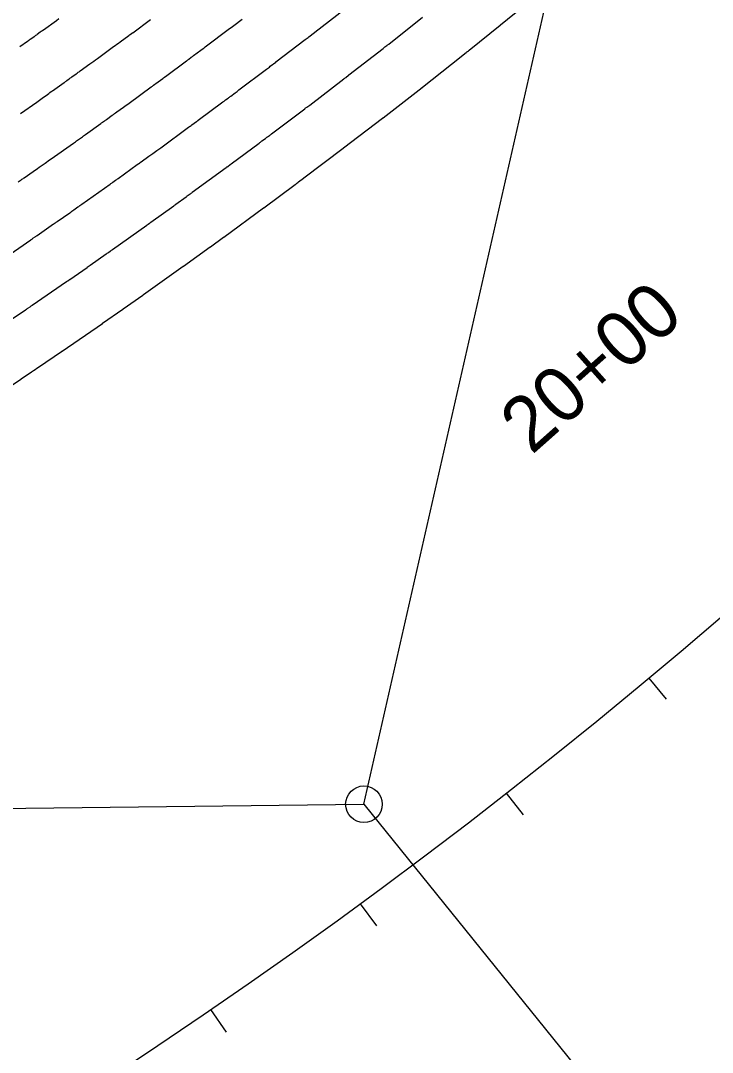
# Model space of a CAD drawing. Extents: x 1710723 to 1713003, y 548603 to 551142.
# Drawn here: x 1712116.1 to 1712191.7, y 549190 to 549302.6 of the extents above; entities that cross this region are included whole.
import ezdxf

# ---------------------------------------------------------------- set-up
doc = ezdxf.new("R2010")
doc.units = 0
for name, color, linetype in [('R_Contours', 7, 'Continuous'), ('R_Horz Alg', 7, 'Continuous'), ('R_Horz Alg Annot', 7, 'Continuous')]:
    doc.layers.add(name, color=color, linetype=linetype)

msp = doc.modelspace()

# ---------------------------------------------------------------- linework, layer by layer
at = {"layer": 'R_Contours'}
for points in [[(1712111.69, 549260.5), (1712116.15, 549263.48), (1712116.18, 549263.5), (1712117.33, 549264.28), (1712117.53, 549264.41), (1712117.72, 549264.54), (1712117.91, 549264.67), (1712118.1, 549264.8), (1712120.6, 549266.5), (1712120.65, 549266.54), (1712120.66, 549266.54), (1712125.06, 549269.57), (1712125.09, 549269.59), (1712127.31, 549271.14), (1712127.34, 549271.16), (1712129.48, 549272.67), (1712129.5, 549272.68), (1712129.53, 549272.7), (1712129.54, 549272.71), (1712133.9, 549275.8), (1712133.93, 549275.83), (1712136.85, 549277.93), (1712136.86, 549277.94), (1712138.29, 549278.97), (1712138.33, 549279), (1712138.33, 549279), (1712142.66, 549282.18), (1712142.7, 549282.2), (1712146.12, 549284.74), (1712146.21, 549284.81), (1712146.3, 549284.88), (1712146.39, 549284.95), (1712146.48, 549285.01), (1712147.02, 549285.41), (1712147.03, 549285.43), (1712147.06, 549285.45), (1712147.07, 549285.45), (1712151.35, 549288.69), (1712151.39, 549288.72), (1712155.65, 549291.98), (1712155.69, 549292.01), (1712155.72, 549292.03), (1712159.97, 549295.34), (1712160, 549295.37), (1712160.01, 549295.37), (1712164.25, 549298.72), (1712164.28, 549298.74), (1712164.78, 549299.14), (1712164.86, 549299.2), (1712164.94, 549299.27), (1712165.03, 549299.34), (1712165.11, 549299.4), (1712168.5, 549302.13), (1712168.53, 549302.15), (1712172.74, 549305.58)], [(1712114.14, 549276.56), (1712117.25, 549278.7), (1712117.3, 549278.74), (1712117.36, 549278.78), (1712117.42, 549278.82), (1712117.48, 549278.86), (1712117.71, 549279.02), (1712117.77, 549279.06), (1712117.82, 549279.1), (1712117.88, 549279.14), (1712117.94, 549279.18), (1712119.46, 549280.24), (1712119.52, 549280.28), (1712119.57, 549280.31), (1712119.63, 549280.35), (1712119.69, 549280.39), (1712119.91, 549280.55), (1712119.96, 549280.58), (1712120.02, 549280.62), (1712120.07, 549280.66), (1712120.13, 549280.7), (1712121.49, 549281.65), (1712121.6, 549281.73), (1712121.71, 549281.81), (1712121.82, 549281.89), (1712121.93, 549281.97), (1712122.38, 549282.28), (1712122.49, 549282.35), (1712122.6, 549282.43), (1712122.71, 549282.51), (1712122.82, 549282.59), (1712125.9, 549284.77), (1712125.97, 549284.83), (1712126.04, 549284.88), (1712126.12, 549284.93), (1712126.19, 549284.98), (1712126.49, 549285.19), (1712126.56, 549285.24), (1712126.63, 549285.29), (1712126.71, 549285.35), (1712126.78, 549285.4), (1712128.87, 549286.9), (1712128.9, 549286.93), (1712128.94, 549286.95), (1712128.97, 549286.98), (1712129.01, 549287), (1712129.15, 549287.11), (1712129.19, 549287.13), (1712129.23, 549287.16), (1712129.26, 549287.18), (1712129.3, 549287.21), (1712130.14, 549287.82), (1712130.25, 549287.9), (1712130.36, 549287.98), (1712130.47, 549288.06), (1712130.57, 549288.13), (1712131.01, 549288.44), (1712131.11, 549288.52), (1712131.22, 549288.6), (1712131.33, 549288.68), (1712131.44, 549288.75), (1712134.48, 549290.98), (1712134.57, 549291.05), (1712134.66, 549291.11), (1712134.74, 549291.18), (1712134.83, 549291.24), (1712135.33, 549291.6), (1712135.37, 549291.63), (1712135.4, 549291.66), (1712135.47, 549291.71), (1712135.51, 549291.73), (1712135.54, 549291.76), (1712138.22, 549293.75), (1712138.29, 549293.8), (1712138.36, 549293.85), (1712138.43, 549293.91), (1712138.5, 549293.96), (1712138.79, 549294.17), (1712138.86, 549294.23), (1712138.93, 549294.28), (1712139, 549294.33), (1712139.08, 549294.39), (1712139.56, 549294.75), (1712139.67, 549294.82), (1712139.77, 549294.9), (1712139.88, 549294.98), (1712139.98, 549295.06), (1712142.99, 549297.33), (1712143.09, 549297.41), (1712143.19, 549297.48), (1712143.3, 549297.56), (1712143.4, 549297.64), (1712144.02, 549298.1), (1712144.02, 549298.11), (1712147.21, 549300.55), (1712147.31, 549300.63), (1712147.42, 549300.71), (1712147.52, 549300.78), (1712147.62, 549300.86), (1712148.23, 549301.33), (1712148.25, 549301.35), (1712151.45, 549303.83)], [(1712114.57, 549269.62), (1712116.68, 549271.06), (1712116.74, 549271.1), (1712116.8, 549271.14), (1712116.86, 549271.19), (1712116.92, 549271.23), (1712117.16, 549271.39), (1712117.22, 549271.43), (1712117.28, 549271.47), (1712117.34, 549271.51), (1712117.4, 549271.55), (1712121.15, 549274.13), (1712121.18, 549274.16), (1712121.21, 549274.18), (1712121.24, 549274.2), (1712121.27, 549274.22), (1712121.39, 549274.3), (1712121.42, 549274.32), (1712121.45, 549274.34), (1712121.48, 549274.36), (1712121.51, 549274.38), (1712123.39, 549275.69), (1712123.42, 549275.71), (1712123.44, 549275.73), (1712123.47, 549275.75), (1712123.5, 549275.77), (1712123.62, 549275.85), (1712123.65, 549275.87), (1712123.68, 549275.89), (1712123.71, 549275.91), (1712123.73, 549275.93), (1712125.49, 549277.16), (1712125.54, 549277.2), (1712125.6, 549277.24), (1712125.66, 549277.28), (1712125.72, 549277.32), (1712125.95, 549277.49), (1712126.01, 549277.53), (1712126.07, 549277.57), (1712126.12, 549277.61), (1712126.18, 549277.65), (1712129.9, 549280.29), (1712129.94, 549280.32), (1712129.97, 549280.34), (1712130.01, 549280.37), (1712130.05, 549280.4), (1712130.2, 549280.51), (1712130.24, 549280.53), (1712130.28, 549280.56), (1712130.32, 549280.59), (1712130.36, 549280.61), (1712132.86, 549282.41), (1712132.89, 549282.44), (1712132.93, 549282.47), (1712133.01, 549282.52), (1712133.03, 549282.53), (1712133.04, 549282.55), (1712133.06, 549282.56), (1712133.08, 549282.57), (1712134.22, 549283.4), (1712134.27, 549283.44), (1712134.33, 549283.48), (1712134.38, 549283.52), (1712134.44, 549283.56), (1712134.66, 549283.72), (1712134.72, 549283.76), (1712134.77, 549283.8), (1712134.83, 549283.84), (1712134.88, 549283.88), (1712138.57, 549286.58), (1712138.62, 549286.61), (1712138.66, 549286.65), (1712138.71, 549286.68), (1712138.75, 549286.71), (1712139.01, 549286.9), (1712139.05, 549286.93), (1712139.09, 549286.96), (1712139.12, 549286.98), (1712142.17, 549289.25), (1712142.25, 549289.31), (1712142.33, 549289.37), (1712142.41, 549289.43), (1712142.49, 549289.49), (1712142.87, 549289.77), (1712142.93, 549289.81), (1712142.98, 549289.85), (1712143.03, 549289.89), (1712143.09, 549289.93), (1712143.31, 549290.09), (1712143.36, 549290.13), (1712143.41, 549290.17), (1712143.47, 549290.21), (1712143.52, 549290.25), (1712147.17, 549293.01), (1712147.22, 549293.05), (1712147.28, 549293.09), (1712147.33, 549293.13), (1712147.38, 549293.17), (1712147.71, 549293.41), (1712147.71, 549293.41), (1712151.43, 549296.26), (1712151.48, 549296.3), (1712151.54, 549296.34), (1712151.59, 549296.39), (1712151.64, 549296.43), (1712151.95, 549296.66), (1712151.98, 549296.69), (1712155.71, 549299.59), (1712155.76, 549299.63), (1712155.81, 549299.67), (1712155.87, 549299.71), (1712155.92, 549299.75), (1712156.13, 549299.91), (1712156.18, 549299.95), (1712156.23, 549299.99), (1712156.28, 549300.03), (1712156.33, 549300.07), (1712160.04, 549302.99)], [(1712115.87, 549285.01), (1712116.2, 549285.24), (1712116.28, 549285.3), (1712116.36, 549285.35), (1712116.44, 549285.41), (1712116.52, 549285.47), (1712117.49, 549286.15), (1712117.66, 549286.26), (1712117.82, 549286.38), (1712117.99, 549286.49), (1712118.15, 549286.61), (1712118.81, 549287.07), (1712118.97, 549287.18), (1712119.14, 549287.3), (1712119.3, 549287.41), (1712119.47, 549287.53), (1712121.9, 549289.26), (1712122.01, 549289.33), (1712122.11, 549289.41), (1712122.22, 549289.49), (1712122.33, 549289.57), (1712122.77, 549289.87), (1712122.88, 549289.95), (1712122.99, 549290.03), (1712123.1, 549290.11), (1712123.2, 549290.18), (1712124.88, 549291.39), (1712124.93, 549291.43), (1712124.98, 549291.46), (1712125.04, 549291.5), (1712125.09, 549291.54), (1712125.3, 549291.69), (1712125.36, 549291.73), (1712125.41, 549291.77), (1712125.46, 549291.81), (1712125.51, 549291.84), (1712126.14, 549292.3), (1712126.27, 549292.39), (1712126.39, 549292.48), (1712126.51, 549292.57), (1712126.64, 549292.65), (1712127.35, 549293.17), (1712127.51, 549293.28), (1712127.67, 549293.4), (1712127.83, 549293.51), (1712127.99, 549293.63), (1712130.38, 549295.39), (1712130.52, 549295.48), (1712130.65, 549295.58), (1712130.78, 549295.67), (1712130.91, 549295.77), (1712131.65, 549296.31), (1712131.7, 549296.34), (1712131.75, 549296.38), (1712131.86, 549296.46), (1712131.88, 549296.48), (1712131.91, 549296.5), (1712131.93, 549296.52), (1712131.96, 549296.54), (1712134.26, 549298.25), (1712134.33, 549298.29), (1712134.39, 549298.34), (1712134.45, 549298.39), (1712134.51, 549298.43), (1712134.76, 549298.62), (1712134.82, 549298.67), (1712134.89, 549298.71), (1712134.95, 549298.76), (1712135.01, 549298.8), (1712135.82, 549299.4), (1712135.97, 549299.52), (1712136.13, 549299.63), (1712136.28, 549299.75), (1712136.44, 549299.86), (1712138.8, 549301.65), (1712138.95, 549301.76), (1712139.11, 549301.88), (1712139.26, 549301.99), (1712139.41, 549302.11), (1712140.33, 549302.79)], [(1712120.3, 549302.81), (1712120.04, 549302.62), (1712118.62, 549301.6), (1712118.54, 549301.54), (1712118.45, 549301.48), (1712118.37, 549301.42), (1712118.28, 549301.36), (1712117.94, 549301.11), (1712117.86, 549301.05), (1712117.77, 549300.99), (1712117.69, 549300.93), (1712117.6, 549300.87), (1712117.25, 549300.61), (1712117.16, 549300.55), (1712117.07, 549300.49), (1712116.98, 549300.42), (1712116.89, 549300.36), (1712116.04, 549299.75)], [(1712116.11, 549292.47), (1712117.9, 549293.74), (1712118.04, 549293.84), (1712118.18, 549293.95), (1712118.33, 549294.05), (1712118.47, 549294.15), (1712119.05, 549294.56), (1712119.2, 549294.66), (1712119.34, 549294.76), (1712119.48, 549294.87), (1712119.63, 549294.97), (1712120.89, 549295.87), (1712120.96, 549295.92), (1712121.03, 549295.98), (1712121.1, 549296.03), (1712121.17, 549296.08), (1712121.45, 549296.28), (1712121.52, 549296.33), (1712121.59, 549296.38), (1712121.66, 549296.43), (1712121.73, 549296.48), (1712122.21, 549296.83), (1712122.32, 549296.9), (1712122.42, 549296.98), (1712122.52, 549297.05), (1712122.63, 549297.13), (1712123.69, 549297.89), (1712123.9, 549298.04), (1712124.11, 549298.2), (1712124.32, 549298.35), (1712124.54, 549298.5), (1712126.29, 549299.79), (1712126.47, 549299.92), (1712126.64, 549300.04), (1712126.81, 549300.17), (1712126.99, 549300.3), (1712127.96, 549301.01), (1712128, 549301.03), (1712128.03, 549301.06), (1712128.07, 549301.08), (1712128.1, 549301.11), (1712128.24, 549301.21), (1712128.28, 549301.24), (1712128.31, 549301.26), (1712128.34, 549301.29), (1712128.38, 549301.31), (1712130.31, 549302.75)]]:
    msp.add_lwpolyline(points, dxfattribs=at)
at = {"layer": 'R_Horz Alg'}
for centre, radius, start, end in [((1711727.02, 549745.3), 532.98, 270.6428, 347.2066), ((1711777.17, 549719.88), 636.62, 271.07865, 340.7734)]:
    msp.add_arc(centre, radius, start, end, dxfattribs=at)
at = {"layer": 'R_Horz Alg Annot'}
for p, q in [((1712153.63, 549217.07), (1712246.77, 549627.28)), ((1711733, 549212.35), (1712153.63, 549217.07))]:
    msp.add_line(p, q, dxfattribs=at)
for points in [[(1712186.68, 549228.53), (1712184.76, 549230.84)], [(1712171.04, 549215.91), (1712169.19, 549218.28)], [(1712153.63, 549217.07), (1712229.02, 549123.72)], [(1712155.02, 549203.79), (1712153.24, 549206.21)], [(1712138.62, 549192.18), (1712136.92, 549194.65)]]:
    msp.add_lwpolyline(points, dxfattribs=at)
msp.add_circle((1712153.63, 549217.07), 2, dxfattribs=at)

# ---------------------------------------------------------------- texts
msp.add_text('20+00', height=6, rotation=41.6088, dxfattribs=at).set_placement((1712171.94, 549255.14))

doc.saveas('drawing.dxf')
